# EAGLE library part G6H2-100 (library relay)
RELAY 2 x switch, 0.5 A/125 V AC, 1 A/30 V DC, Omron
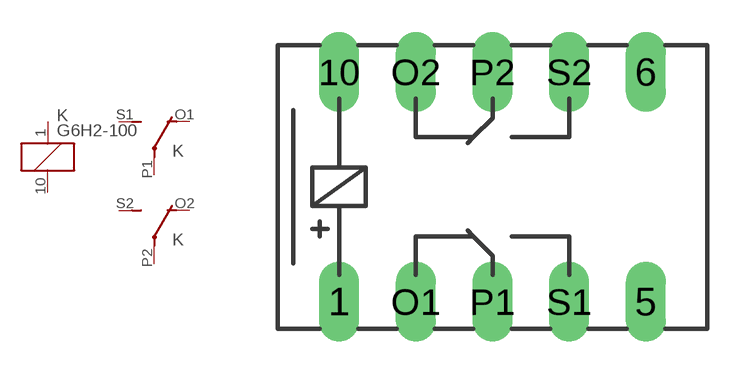
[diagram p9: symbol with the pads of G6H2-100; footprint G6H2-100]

Designator prefix K; gates 1=K 2=U 3=U

## G6H2-100 (OC_FARNELL: unknown; OC_NEWARK: unknown)  [G6H2-100]
1  1:1  pas
10  1:2  pas
O1  2:O  pas
O2  3:O  pas
P1  2:P  pas
P2  3:P  pas
S1  2:S  pas
S2  3:S  pas

## Footprint G6H2-100 (pad centres in mm)
RELAY 2 x switch 0.5 A/125 V AC, 1 A/30 V DC, Omron
drill 0.813 long: 1 -5.08,-3.81; 5 5.08,-3.81; 6 5.08,3.81; 10 -5.08,3.81; O1 -2.54,-3.81; O2 -2.54,3.81; P1 0,-3.81; P2 0,3.81; S1 2.54,-3.81; S2 2.54,3.81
